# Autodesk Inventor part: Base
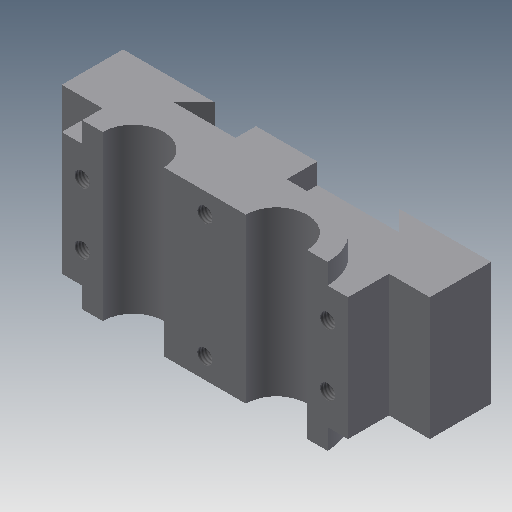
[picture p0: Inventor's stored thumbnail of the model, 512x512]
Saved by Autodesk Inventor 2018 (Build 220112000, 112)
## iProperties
Shininess: 77.0
Length Units: 11269
Angle Units: 11279
Time Units: 11290
Mass Units: 11283
Length Display Precision: 3
Angle Display Precision: 2
Created: 2002-02
Part Number: Base
Document SubType Name: Modeling
Designer: ***
Density: 1 g/cm^3
Material: Generic
Appearance: Default
Density: 0.0
Volumn: 0.0
Area: 0.0
PropertySet Name: Model Information
Control State: 0
Master: False
Checked Out: False
Author: ***
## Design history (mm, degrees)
sketch "Sketch2"
  geometry: L1 (-10.066, -1.263)-(24.934, -1.263); L2 (37.434, 11.237)-(32.434, 11.237); L3 (17.434, 11.237)-(-2.566, 11.237); L4 (-17.566, 11.237)-(-22.566, 11.237); A1 r 12.5 centre (-10.066, 11.237) between (-22.566, 11.237) and (-10.066, -1.263); A2 r 12.5 centre (24.934, 11.237) between (24.934, -1.263) and (37.434, 11.237); A3 r 7.5 centre (24.934, 11.237) between (17.434, 11.237) and (32.434, 11.237); A4 r 7.5 centre (-10.066, 11.237) between (-17.566, 11.237) and (-2.566, 11.237)
  constraints: 8 end point, 8 point on circle, 4 centre point, 3 horizontal, 3 parallel, 2 coincident, 2 equal radius, 2 tangent
  dimensions: "d0" = 12.5 radius of A1; "d1" = 7.5 radius of A4; "d2" = 35 distance of A1.centre A2.centre; "d3" = 12.5 distance between parallel lines of L3 L1
extrude "Extrusion1" new body sketch "Sketch2" stored distance "d4" = 40; taper "d5" = 0 deg
sketch "Sketch4"
  geometry: L1 (-27.566, 1.237)-(-37.566, 1.237); L2 (-37.566, 1.237)-(-37.566, -13.763); L3 (-37.566, -13.763)-(-15.066, -13.763); L4 (-15.066, -13.763)-(-20.066, -8.763); L5 (-20.066, -8.763)-(34.934, -8.763); L6 (34.934, -8.763)-(29.934, -13.763); L7 (29.934, -13.763)-(52.434, -13.763); L8 (52.434, -13.763)-(52.434, 1.237); L9 (52.434, 1.237)-(42.434, 1.237); L10 (24.934, -1.263)-(-10.066, -1.263); L11 (-17.566, 11.237)-(-22.566, 11.237) reference; L12 (37.434, 11.237)-(32.434, 11.237) reference; L13 (-22.566, 11.237)-(-27.566, 11.237); L14 (-27.566, 11.237)-(-27.566, 1.237); L15 (37.434, 11.237)-(42.434, 11.237); L16 (42.434, 11.237)-(42.434, 1.237); A1 r 12.5 centre (24.934, 11.237) between (24.934, -1.263) and (37.434, 11.237); A2 r 12.5 centre (-10.066, 11.237) between (-22.566, 11.237) and (-10.066, -1.263); A3 r 12.5 centre (24.934, 11.237) between (24.934, -1.263) and (37.434, 11.237) reference; A4 r 12.5 centre (-10.066, 11.237) between (-22.566, 11.237) and (-10.066, -1.263) reference
  constraints: 28 end point, 6 perpendicular, 5 equal length, 4 concentric, 4 parallel, 4 point on circle, 2 centre point, 2 collinear, 1 tangent
  dimensions: "d12" = 15 distance of L1.end L2.end; "d13" = 25 distance from line of L3 L11.end; "d14" = 90 distance between parallel lines of L2 L8; "d15" = 5 distance between parallel lines of L5 L7; "d16" = 22.5 distance of L2.end L3.end; "d24" = 5 distance of L12.start L15.end; "d25" = 15 distance from line of L8 L12.start
extrude "Extrusion3" join sketch "Sketch4" stored distance "d17" = 30; taper "d18" = 0 deg
sketch "Sketch5"
  geometry: L1 (-14.934, -1.263)-(0.066, -1.263); L2 (0.066, -1.263)-(0.066, -8.763); L3 (0.066, -8.763)-(-14.934, -8.763); L4 (-14.934, -8.763)-(-14.934, -1.263); L5 (10.066, -1.263)-(-24.934, -1.263) reference; 1 further point
  constraints: 8 end point, 2 parallel, 1 collinear, 1 horizontal, 1 perpendicular
  dimensions: "d19" = 7.5 distance of L1.end L2.end; "d20" = 15 distance of L2.end L3.end; "d21" = 15 distance from line of point (-29.934, -13.763) L4
extrude "Extrusion4" join sketch "Sketch5" distance "d22" = 40; taper "d23" = 0 deg
sketch "Sketch6"
  geometry: L1 (-5, -35)-(0, -35) reference; L2 (-5, -35)-(-5, -5) reference; 1 further point
  dimensions: "d26" = 7.5 distance from line of L1 point (0, -27.5); "d27" = 5 distance from line of L2 point (0, -27.5)
hole "Hole1" sketch "Sketch6" at (0, -27.5) diameter "d28" = 3.688; stored, may be unused: countersink angle "d32" = 82 deg, drill point angle "d34" = 0 deg; dims "d29" = 9, "d30" = 4, "d31" = 2, "d33" = 15
pattern_linear "Rectangular Pattern1" dims "d37" = 60, "d40" = 15
sketch "Sketch7"
  geometry: L1 (-20, -40)-(-20, -35) reference; L2 (0, -40)-(20, -40) reference; 1 further point
  dimensions: "d41" = 30 distance from line of L1 point (10, -35); "d42" = 5 distance from line of L2 point (10, -35)
hole "Hole2" sketch "Sketch7" at (10, -35) diameter "d43" = 3.688; stored, may be unused: countersink angle "d47" = 82 deg, drill point angle "d49" = 0 deg; dims "d44" = 9, "d45" = 4, "d46" = 2, "d48" = 15
pattern_linear "Rectangular Pattern2" dims "d52" = 30
body "Solid1"
